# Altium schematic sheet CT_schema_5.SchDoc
size 287 x 163 mm
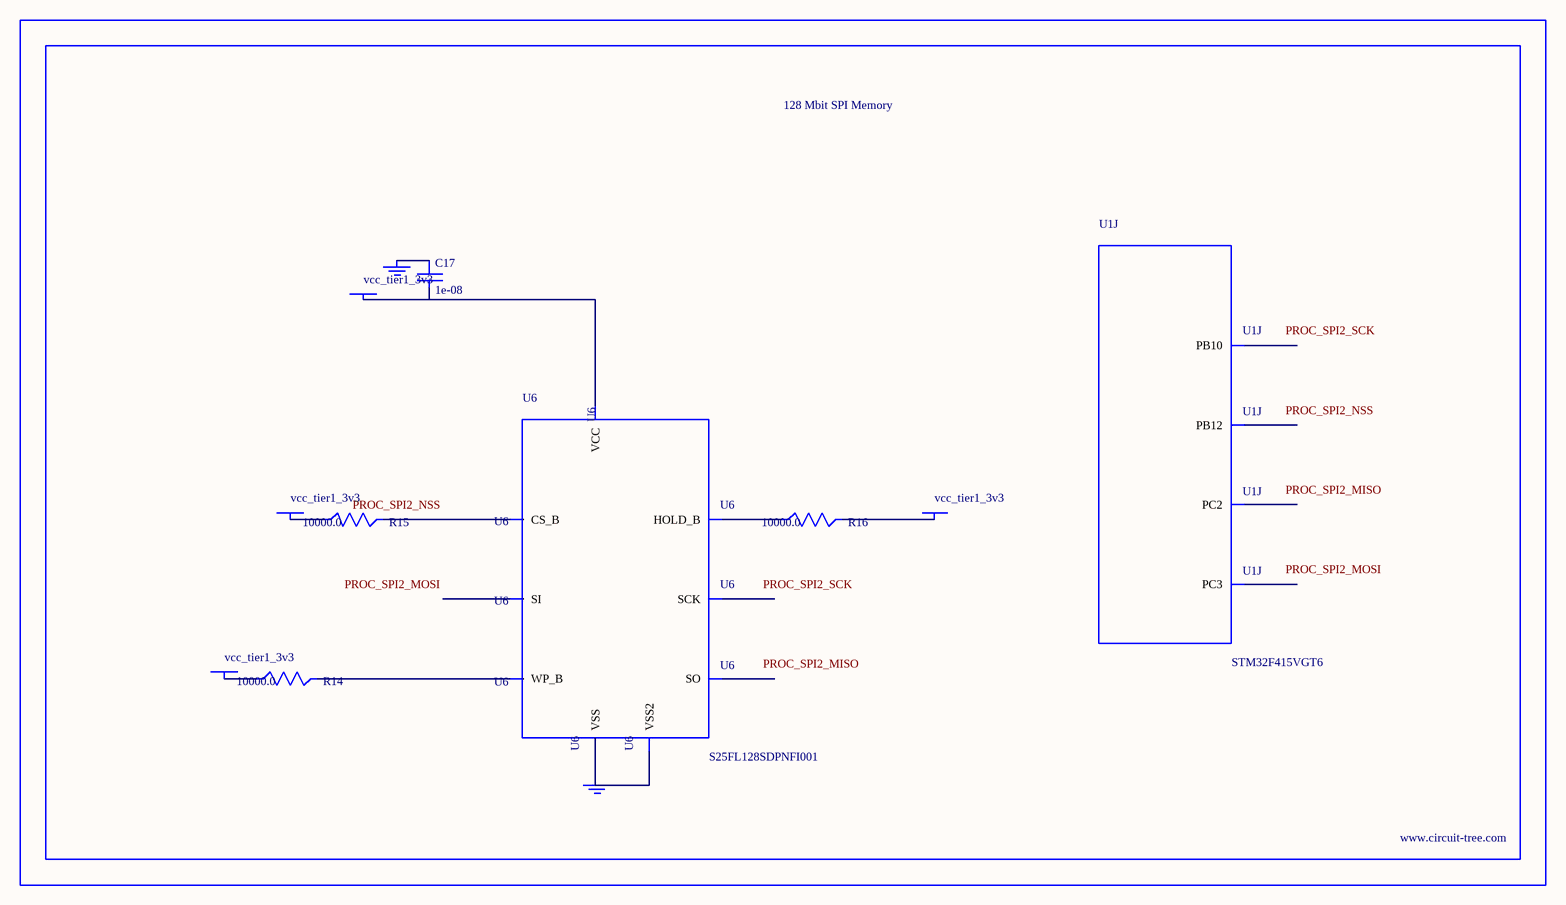
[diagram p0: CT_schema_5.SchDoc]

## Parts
BORDER4  (no value)
C17  1e-08  [C0402]
GND_INSTANCE_4_0  (no value)
GND_INSTANCE_4_1  (no value)
POWER_INSTANCE_4_0  vcc_tier1_3v3
POWER_INSTANCE_4_1  vcc_tier1_3v3
POWER_INSTANCE_4_2  vcc_tier1_3v3
POWER_INSTANCE_4_3  vcc_tier1_3v3
R14  10000.0  [R0603]
R15  10000.0  [R0603]
R16  10000.0  [R0603]
U1  STM32F415VGT6  [LQFP100]  (part J of 11)
U6  S25FL128SDPNFI001  [WNG008]

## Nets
NetC17_1: C17.1 GND_INSTANCE_4_0.0(GND)
NetC17_2: C17.2 POWER_INSTANCE_4_3.0(PWR) U6.8(VCC)
NetGND_INSTANCE_4_1_0: GND_INSTANCE_4_1.0(GND) U6.4(VSS) U6.PAD(VSS2)
NetPOWER_INSTANCE_4_0_0: POWER_INSTANCE_4_0.0(PWR) R15.1
NetPOWER_INSTANCE_4_1_0: POWER_INSTANCE_4_1.0(PWR) R14.1
NetPOWER_INSTANCE_4_2_0: POWER_INSTANCE_4_2.0(PWR) R16.2
NetR14_2: R14.2 U6.3(WP_B)
NetR15_2: R15.2 U6.1(CS_B)
NetR16_1: R16.1 U6.7(HOLD_B)

Not connected (* = marked no-connect by the designer): U1 17(PC2) 18(PC3) 47(PB10) 51(PB12); U6 2(SO) 5(SI) 6(SCK)

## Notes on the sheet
- Labels drawn without touching a wire or pin: PROC_SPI2_MISO, PROC_SPI2_MOSI, PROC_SPI2_NSS, PROC_SPI2_SCK

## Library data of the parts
BORDER4 = BORDER_PAGE4
C17 = C0402C103K3RAC
GND_INSTANCE_4_0 GND_INSTANCE_4_1 = GND
POWER_INSTANCE_4_0-POWER_INSTANCE_4_3 = PWR
R14-R16 = RC0603JR-0710KL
